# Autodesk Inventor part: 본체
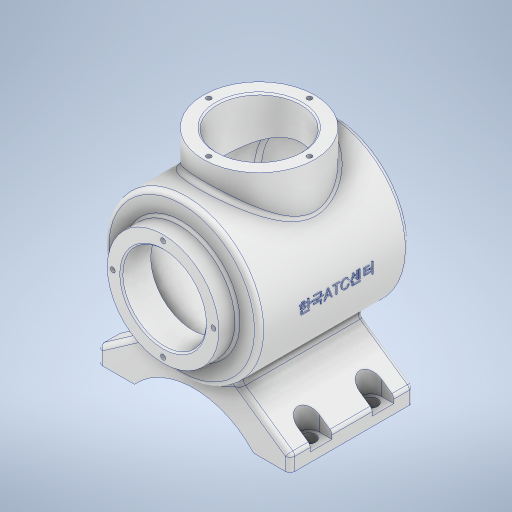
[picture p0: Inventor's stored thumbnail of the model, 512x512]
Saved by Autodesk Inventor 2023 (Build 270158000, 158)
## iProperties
Created: 2023-12
Part Number: 본체
Material: 알루미늄 6061
Document SubType Name: Modeling
Designer: asung
Density: 2.7 g/cm^3
Appearance: 알루미늄 - 평지
Mass: 1284.19 g
Surface Area: 1061.41 cm^2
Volume: 475.627 cm^3
Author: asung
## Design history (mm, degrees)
sketch "스케치1"
  geometry: L1 (0, 32.119)-(0, -87.881); L2 (37.684, 20.119)-(50, 20.119); L3 (50, 20.119)-(50, -76.217); L4 (0, 32.119)-(36, 32.119); L5 (36, 32.119)-(36, 21.803); L6 (291.691, 110.874)-(291.691, -9.126); L7 (291.691, 110.874)-(327.691, 110.874); L8 (327.691, 110.874)-(327.691, 98.874); L9 (327.691, 98.874)-(341.691, 98.874); L10 (341.691, 98.874)-(341.691, 2.537); A1 r 1.684 centre (37.684, 21.803) between (36, 21.803) and (37.684, 20.119); A2 r 113 centre (0, 25.119) between (0, -87.881) and (50, -76.217); A3 r 113 centre (291.691, 103.874) between (291.691, -9.126) and (341.691, 2.537); 6 further points
  constraints: 20 end point, 6 point on circle, 3 centre point, 3 horizontal, 3 perpendicular, 3 vertical, 2 symmetric about line, 2 tangent, 2 vertical alignment, 1 midpoint, 1 point on line
  dimensions: "d0" = 120 distance of L1.end L1.start; "d11" = 100 diameter of L3 L1; "d34" = 72 diameter of L5 L1; "d36" = 113 radius of A2; "d38" = 108 distance from line of L1.end L2; "d39" = 120 vertical distance of L1.end L4.end; "d93" = 120 distance of L6.end L6.start; "d94" = 36 distance of L6.start L7.end; "d95" = 12 distance of L7.end L8.end; "d96" = 100 diameter of L10 L6; "d97" = 113 radius of A3
revolve "회전1" sketch "스케치1" stored, may be unused: angle "d5" = 90 deg
sketch "스케치2"
  geometry: L1 (50, 20.119)-(50, -76.217) reference; L2 (-50, -76.217)-(-50, 20.119) reference; L3 (0, 32.119)-(0, -92.812); L4 (-36, 32.119)-(36, 32.119) reference; L5 (36, 32.119)-(36, 21.803) reference; L6 (37.684, 20.119)-(50, 20.119) reference; L7 (-50, 20.119)-(-37.684, 20.119) reference; L8 (-36, 21.803)-(-36, 32.119) reference; L9 (0, 32.119)-(27, 32.119); L10 (-36, 32.119)-(36, 32.119) reference; L11 (-50, 20.119)-(50, 20.119) reference; L12 (27, 32.119)-(27, 13.119); L13 (27, 13.119)-(40, 13.119); L14 (43, 10.119)-(43, -69.797); A1 r 1.684 centre (37.684, 21.803) between (36, 21.803) and (37.684, 20.119) reference; A2 r 1.684 centre (-37.684, 21.803) between (-37.684, 20.119) and (-36, 21.803) reference; A3 r 113 centre (0, 25.119) between (0, -87.881) and (50, -76.217) reference; A4 r 113 centre (0, 25.119) between (-50, -76.217) and (0, -87.881) reference; A5 r 3 centre (40, 10.119) between (43, 10.119) and (40, 13.119); A6 r 106 centre (0, 25.119) between (0, -80.881) and (41.165, -72.561); A7 r 3 centre (40, -69.797) between (41.165, -72.561) and (43, -69.797); 5 further points
  constraints: 10 end point, 7 point on circle, 3 centre point, 3 tangent, 2 point on line, 1 horizontal, 1 midpoint, 1 perpendicular
  dimensions: "d12" = 27 distance of L3.start L9.end; "d14" = 19 distance of L9.end L12.end; "d42" = 3 radius of A5 (derived); "d98" = 7 radial gap between concentric circles of A4 A6; "d99" = 3 radius of A7 (derived)
revolve "회전2" sketch "스케치2" stored, may be unused: angle "d16" = 90 deg
node "작업 평면1"
sketch "스케치3"
  geometry: L1 (0, 0)-(0, -77); L2 (-38.5, -77)-(-62, -77); L3 (-62, -77)-(-62, -68.562); L4 (-60.721, -66.104)-(-26.694, -42.278); L5 (38.5, -77)-(62, -77); L6 (62, -77)-(62, -68.562); L7 (60.721, -66.104)-(26.694, -42.278); C1 r 42.236 at (0, 0) reference; A1 r 3 centre (-59, -68.562) between (-60.721, -66.104) and (-62, -68.562); A2 r 3 centre (59, -68.562) between (62, -68.562) and (60.721, -66.104); A3 r 52.096 centre (0, -112.096) between (38.5, -77) and (-38.5, -77); 5 further points
  constraints: 14 end point, 7 point on circle, 7 symmetric about line, 4 point on line, 3 centre point, 2 tangent, 1 horizontal, 1 perpendicular, 1 vertical, 3 other
  dimensions: "d22" = 55 deg angle of L4 L3; "d25" = 3 radius of A1 (derived); "d26" = 17 distance of L1.end point (0, -60); "d27" = 124 distance of L5.end L2.end; "d28" = 77 distance of L5.start L2.start; "d92" = 10 distance of point (62, -67) L5.end
extrude "돌출1" join sketch "스케치3" distance "d29" = 80; taper "d30" = 0 deg
fillet "모깎기1" dims "d31" = 3
fillet "모깎기2" dims "d32" = 3
node "작업 평면2"
sketch "스케치4"
  geometry: L1 (-11.926, 80)-(20.5, 80) reference; L2 (23.5, 77)-(23.5, 3) reference; L3 (15.5, 67)-(23.5, 67); L4 (15.5, 53)-(23.5, 53); C1 r 4.5 at (15.5, 60); A1 r 7 centre (15.5, 60) between (15.5, 67) and (15.5, 53); 1 further point
  constraints: 4 end point, 2 centre point, 2 perpendicular, 2 point on circle, 2 point on line, 1 coincident
  dimensions: "d44" = 9 diameter of C1; "d45" = 20 distance from line of L1 C1.centre; "d46" = 8 distance from line of L2 C1.centre; "d47" = 14 diameter of A1
extrude "돌출2" cut sketch "스케치4" distance "d48" = 80; taper "d49" = 0 deg
extrude "돌출3" cut sketch "스케치4" distance "d50" = 30; taper "d51" = 0 deg
fillet "모깎기3" dims "d55" = 3
node "작업 평면3"
sketch "스케치5"
  geometry: L1 (-74.5, 100)-(-2.5, 100) reference; C1 r 36 at (-38.5, 38); 2 further points
  constraints: 1 centre point, 1 midpoint, 1 vertical alignment
  dimensions: "d57" = 72 diameter of C1; "d58" = 62 distance from line of C1.centre L1
extrude "돌출4" join sketch "스케치5" stored distance "d59" = 30; taper "d60" = 0 deg
sketch "스케치6"
  geometry: C1 r 36 at (0, 0) reference; 2 further points
  constraints: 1 coincident
hole "구멍1" sketch "스케치6" at (0, 0) diameter "d61" = 54; stored, may be unused: countersink angle "d65" = 90 deg, drill point angle "d67" = 0 deg; dims "d62" = 6, "d63" = 4, "d64" = 2, "d66" = 50
chamfer "모따기1" distance "d68" = 1; stored, may be unused: second distance "d69" = 2, angle "d70" = 45 deg
sketch "스케치7"
  geometry: L1 (30.135, 35)-(30.135, -39) reference; C1 r 36 at (0, 0) reference; C2 r 28 at (0, 0) reference; A1 r 32.5 centre (0, 0) between (0, 32.5) and (32.5, 0); 3 further points
  constraints: 4 point on circle, 1 centre point, 1 coincident
  dimensions: "d71" = 65 diameter of A1; "d72" = 62.63545 distance from line of L1 point (-32.5, 0)
hole "구멍2" sketch "스케치7" at (0, 32.5), (32.5, 0), (0, -32.5), (-32.5, 0) diameter "d73" = 3.242; stored, may be unused: countersink angle "d77" = 90 deg, drill point angle "d79" = 118 deg; dims "d74" = 8, "d75" = 4, "d76" = 2, "d78" = 10
sketch "스케치8"
  geometry: A1 r 32.5 centre (0, 0) between (0, 32.5) and (32.5, 0); 3 further points
  constraints: 4 point on circle, 1 centre point, 1 coincident
  dimensions: "d80" = 65 diameter of A1
hole "구멍3" sketch "스케치8" at (0, 32.5), (32.5, 0), (0, -32.5), (-32.5, 0) diameter "d81" = 3.242; stored, may be unused: countersink angle "d85" = 90 deg, drill point angle "d87" = 118 deg; dims "d82" = 8, "d83" = 4, "d84" = 2, "d86" = 10
node "작업 평면4"
sketch "스케치9"
  geometry: L1 (-47, 48.168)-(47, 48.168) reference; L2 (-36, 60.168)-(36, 60.168) reference; 3 further points
  constraints: 1 midpoint, 1 vertical alignment, 1 other
  dimensions: "d88" = 62 distance from line of L2 point (0, -1.832)
feature "엠보싱1" sketch "스케치9" dims "d5" = 90 deg, "d89" = 0.5, "d90" = 0
fillet "모깎기4" dims "d91" = 3
feature "Ł耀Ń耀Ņ耀Ň耀ŉ耀ŋ耀ō耀ŏ耀" dims "d0" = 120, "d5" = 90 deg, "d11" = 100, "d12" = 27, "d14" = 19, "d16" = 90 deg, "d17" = -20, "d22" = 55 deg, "d25" = 3 (derived), "d26" = 17, "d27" = 124, "d28" = 77, "d29" = 80, "d30" = 0, "d31" = 3, "d32" = 3, "d34" = 72, "d36" = 113, "d38" = 108, "d39" = 120, "d42" = 3 (derived), "d43" = -6, "d44" = 9, "d45" = 20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
node "솔리드1"
pattern_linear "직사각형 패턴1" dims "d54" = 40
mirror "미러1"
node "투영된 루프1"
node "절단 모서리 투영1"
node "절단 모서리 투영2"
feature "A9D066F2-1C7D-4E18-AEED-F7BC21143FA4" dims "d61" = 54, "d62" = 6, "d63" = 4, "d64" = 2, "d65" = 90 deg, "d66" = 50, "d67" = 0
